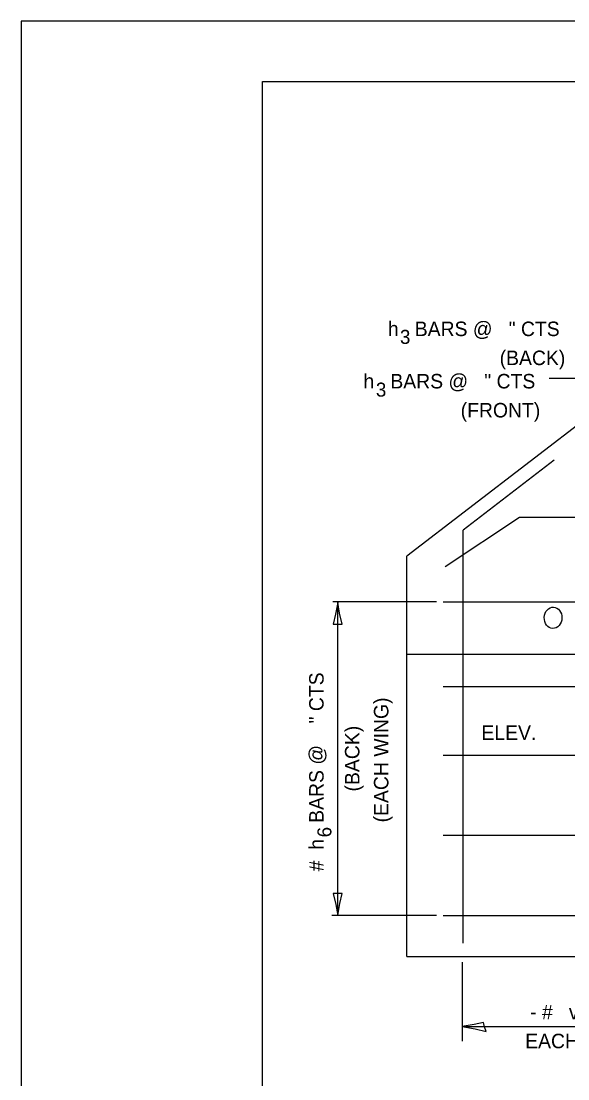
# Model space of a CAD drawing. Extents: x 2133490 to 2172050, y 2138301 to 2145980.
# Drawn here: x 2136350.1 to 2136576.6, y 2145236.7 to 2145674.5 of the extents above; entities that cross this region are included whole.
import ezdxf

# ---------------------------------------------------------------- set-up
doc = ezdxf.new("R2010")
doc.units = 0
for name, color, linetype in [('Level 40', 7, 'Continuous'), ('Level 63', 7, 'Continuous'), ('ROW_PR_Notes', 7, 'Continuous'), ('Sheets_50 Reference Boundary', 7, 'Continuous'), ('Sheets_General Details', 7, 'Continuous'), ('Sheets_Printer Plotting Border', 7, 'Continuous'), ('Topo_Bridge Structures', 7, 'Continuous')]:
    doc.layers.add(name, color=color, linetype=linetype)

msp = doc.modelspace()

# ---------------------------------------------------------------- linework, layer by layer
at = {"layer": 'Level 40'}
msp.add_ellipse((2136570.48, 2145427.55), major_axis=(-0.17, -4.39), ratio=0.834131, dxfattribs=at)
at = {"layer": 'Level 63'}
for p, q in [((2136602.65, 2145526.62), (2136568.85, 2145526.62)), ((2136522.17, 2145434.1), (2136479.28, 2145434.1)), ((2136481.26, 2145304.4), (2136481.26, 2145433.94)), ((2136522.17, 2145304.4), (2136478.76, 2145304.4)), ((2136532.81, 2145285.06), (2136532.81, 2145252.4)), ((2136532.81, 2145258.4), (2136632.9, 2145258.4))]:
    msp.add_line(p, q, dxfattribs=at)
msp.add_lwpolyline([(2136542.81, 2145256.31), (2136542, 2145258.23), (2136541.68, 2145260.08), (2136537.81, 2145259.27), (2136532.81, 2145258.4), (2136538.15, 2145257.43)], close=True, dxfattribs=at)
at = {"layer": 'ROW_PR_Notes'}
for p, q in [((2136623.27, 2145540.13), (2136509.85, 2145453.03)), ((2136570.89, 2145492.74), (2136533.27, 2145463.85)), ((2136525.75, 2145448.75), (2136556.5, 2145469.13)), ((2136556.5, 2145469.13), (2136708.19, 2145469.13)), ((2136533.27, 2145292.92), (2136533.27, 2145463.85)), ((2136509.85, 2145287.36), (2136509.85, 2145453.03)), ((2136525.01, 2145434.1), (2136708.19, 2145434.1)), ((2136843.46, 2145412.33), (2136509.85, 2145412.33)), ((2136525.01, 2145399.07), (2136708.19, 2145399.07)), ((2136525.01, 2145370.67), (2136656.12, 2145370.67)), ((2136525.01, 2145337.54), (2136656.12, 2145337.54)), ((2136525.01, 2145304.4), (2136656.12, 2145304.4)), ((2136509.85, 2145287.36), (2136664.52, 2145287.36))]:
    msp.add_line(p, q, dxfattribs=at)
at = {"layer": 'Sheets_50 Reference Boundary'}
msp.add_lwpolyline([(2136450.12, 2145649.45), (2138025.12, 2145649.45), (2138025.12, 2144649.46), (2136450.12, 2144649.46)], close=True, dxfattribs=at)
at = {"layer": 'Sheets_General Details'}
for p, q in [((2136350.12, 2145674.46), (2136350.12, 2144574.46)), ((2138050.12, 2145674.46), (2136350.12, 2145674.46))]:
    msp.add_line(p, q, dxfattribs=at)
msp.add_lwpolyline([(2136450.12, 2145649.46), (2138025.12, 2145649.46), (2138025.12, 2144599.46), (2136450.12, 2144599.46)], close=True, dxfattribs=at)
at = {"layer": 'Sheets_Printer Plotting Border'}
msp.add_lwpolyline([(2136350.12, 2144574.46), (2138050.12, 2144574.46), (2138050.12, 2145674.46), (2136350.12, 2145674.46)], close=True, dxfattribs=at)
at = {"layer": 'Topo_Bridge Structures'}
for points in [[(2136479.35, 2145424.85), (2136481.26, 2145424.84), (2136483.16, 2145424.84), (2136482.04, 2145429.39), (2136481.26, 2145433.94), (2136480.37, 2145429.09)], [(2136483.16, 2145313.5), (2136481.26, 2145313.51), (2136479.35, 2145313.51), (2136480.47, 2145308.95), (2136481.26, 2145304.4), (2136482.14, 2145309.26)]]:
    msp.add_lwpolyline(points, close=True, dxfattribs=at)

# ---------------------------------------------------------------- texts
at = {"layer": 'Level 63'}
for s, height, p in [('     h   BARS @   " CTS', 6, (2136490.88, 2145544.12)), ('3', 5.8, (2136507.05, 2145540.9)), ('(BACK)', 6, (2136548.34, 2145532.12)), ('     h   BARS @   " CTS', 6, (2136480.77, 2145522.46)), ('3', 5.8, (2136497.07, 2145519.07)), ('(FRONT)', 6, (2136532.19, 2145510.46)), ('  - #   v  BARS', 6, (2136556.53, 2145261.4)), ('EACH WING', 6, (2136558.9, 2145249.4))]:
    msp.add_text(s, height=height, dxfattribs=at).set_placement(p)
for s, height, p in [('   #  h   BARS @    " CTS', 6, (2136475.43, 2145315.93)), ('(EACH WING)', 6, (2136502.26, 2145342.86)), ('(BACK)', 6, (2136490.26, 2145355.66)), ('6', 5.8, (2136478.64, 2145336.68))]:
    msp.add_text(s, height=height, rotation=90, dxfattribs=at).set_placement(p)
at = {"layer": 'ROW_PR_Notes'}
msp.add_text('ELEV.       ', height=6, dxfattribs=at).set_placement((2136540.79, 2145376.98))

doc.saveas('drawing.dxf')
